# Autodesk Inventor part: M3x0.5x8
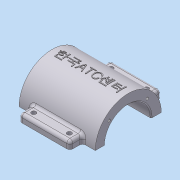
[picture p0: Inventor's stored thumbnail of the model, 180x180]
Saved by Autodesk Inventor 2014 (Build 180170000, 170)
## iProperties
Company: 한국ATC센터
Created: 2009-02
Part Number: M3x0.5x8
Document SubType Name: Modeling
Designer: KYOUNG IL JANG
Density: 2.71 g/cm^3
Mass: 199.243 g
Surface Area: 195.422 cm^2
Volume: 73.5215 cm^3
Material: 알루미늄-6061
Vendor: CBT Solutions
Appearance: 알루미늄 - 평지
Author: KYOUNG IL JANG
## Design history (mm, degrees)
sketch "스케치1"
  geometry: L1 (-45, 40)-(45, 40); L2 (45, 40)-(45, -40); L3 (45, -40)-(-45, -40); L4 (-45, -40)-(-45, 40); 3 further points
  constraints: 8 end point, 2 midpoint, 2 parallel, 1 horizontal, 1 horizontal alignment, 1 perpendicular, 1 vertical alignment
  dimensions: "d0" = 90 distance of L2.end L3.end; "d1" = 80 distance of L1.end L2.end
extrude "돌출1" new body sketch "스케치1" distance "d2" = 10; taper "d3" = 0 deg
sketch "스케치2"
  geometry: L1 (40, 0)-(-40, 0) reference; C1 r 32.5 at (0, 80); 2 further points
  constraints: 1 centre point, 1 midpoint, 1 vertical alignment
  dimensions: "d4" = 65 diameter of C1; "d5" = 80 distance from line of C1.centre L1
extrude "돌출2" join sketch "스케치2" stored distance "d6" = 75; taper "d7" = 0 deg
sketch "스케치3"
  geometry: L1 (-7.5, -20)-(7.5, -20); L2 (7.5, 20)-(-7.5, 20); A1 r 20 centre (7.5, 0) between (7.5, -20) and (7.5, 20); A2 r 20 centre (-7.5, 0) between (-7.5, 20) and (-7.5, -20); 2 further points
  constraints: 4 end point, 4 point on circle, 4 tangent, 2 centre point, 1 horizontal, 1 horizontal alignment, 1 midpoint, 1 parallel, 1 vertical alignment
  dimensions: "d8" = 20 radius of A2; "d9" = 55 dimension on A1 A2
extrude "돌출3" join sketch "스케치3" stored distance "d10" = 75; taper "d11" = 0 deg
fillet "모깎기1" dims "d12" = 10
sketch "스케치4"
  geometry: L1 (-45, 0)-(-45, 10) reference; L2 (37.5, 47.5)-(-37.5, 47.5) reference; L3 (-45, 10)-(-27.513, 47.5); 1 further point
  constraints: 2 end point, 1 point on line
  dimensions: "d13" = 25 deg angle of L3 L1
sketch "스케치5"
  geometry: L1 (-40, 0)-(-40, 10) reference; L2 (-40, 10)-(-22.912, 56.95); 2 further points
  constraints: 2 end point, 2 other
  dimensions: "d14" = 20 deg angle of L2 L1
feature "리브1" dims "d15" = 1, "d16" = 6, "d17" = 0
feature "리브2" dims "d18" = 1, "d19" = 6, "d20" = 0
fillet "모깎기2" dims "d21" = 3
fillet "모깎기3" dims "d22" = 3
fillet "모깎기4" dims "d23" = 3
fillet "모깎기5" dims "d24" = 3
fillet "모깎기6" dims "d25" = 3
fillet "모깎기7" dims "d26" = 3
fillet "모깎기8" dims "d27" = 3
sketch "스케치6"
  geometry: A1 r 10 centre (35, -30) between (35, -40) and (45, -30) reference; 1 further point
hole "구멍1" sketch "스케치6" at (35, -30) diameter "d28" = 10; stored, may be unused: countersink angle "d32" = 90 deg, drill point angle "d34" = 118 deg; dims "d29" = 6, "d30" = 4, "d31" = 2, "d33" = 8
hole "구멍2" diameter "d37" = 45; stored, may be unused: countersink angle "d41" = 90 deg, drill point angle "d43" = 118 deg; dims "d35" = 10, "d36" = 10, "d38" = 6, "d39" = 4, "d40" = 2, "d42" = 8
sketch "스케치7"
  geometry: C1 r 22.5 at (0, 0) reference; 2 further points
  dimensions: "d44" = 135 deg dimension on C1.centre point (-18.738, 18.738) point (80, 0); "d45" = 26.5 distance of point (-18.738, 18.738) C1.centre
hole "구멍3" sketch "스케치7" at (-18.738, 18.738) diameter "d46" = 2.459; stored, may be unused: countersink angle "d50" = 90 deg, drill point angle "d52" = 118 deg; dims "d47" = 8, "d48" = 4, "d49" = 2, "d51" = 10
node "작업 평면1"
chamfer "모따기1" distance "d69" = 1; stored, may be unused: second distance "d70" = 2, angle "d71" = 45 deg
sketch "스케치9"
  geometry: L1 (-31.623, 87.5)-(-45, 87.5); L2 (-45, 87.5)-(-45, 72.5); L3 (-45, 72.5)-(-31.623, 72.5); A1 r 32.5 centre (0, 80) between (-31.623, 87.5) and (-31.623, 72.5) reference; 1 further point
  constraints: 6 end point, 2 parallel, 2 point on circle, 1 horizontal, 1 perpendicular
  dimensions: "d73" = 15 distance of L1.end L2.end; "d74" = 45 distance from line of A1.centre L2
extrude "돌출5" join sketch "스케치9" stored distance "d75" = 50; taper "d76" = 0 deg
fillet "모깎기10" dims "d77" = 3
fillet "모깎기11" dims "d78" = 3
sketch "스케치10"
  geometry: L1 (100.378, 66.389)-(0, 66.389); L2 (0, 66.389)-(0, -76.978); L3 (0, -76.978)-(100.378, -76.978); L4 (100.378, -76.978)-(100.378, 66.389); C1 r 32.5 at (0, 0) reference; 1 further point
  constraints: 8 end point, 2 parallel, 1 horizontal, 1 perpendicular, 1 point on line
extrude "돌출6" cut sketch "스케치10" stored distance "d79" = 10; taper "d80" = 0 deg
sketch "스케치11"
  geometry: C1 r 1.621 at (4.5, 4) reference; C2 r 1.621 at (39.5, 4) reference; 1 further point
hole "구멍5" sketch "스케치11" at (39.5, 4), (4.5, 4) diameter "d81" = 4.5; stored, may be unused: countersink angle "d85" = 90 deg, drill point angle "d87" = 118 deg; dims "d82" = 6, "d83" = 4, "d84" = 2, "d86" = 8
node "작업 평면2"
sketch "스케치12"
  geometry: 2 further points
  constraints: 1 coincident, 1 other
feature "엠보싱1" sketch "스케치12" dims "d8" = 20, "d9" = 55, "d88" = 0.5, "d89" = 0
node "솔리드1"
mirror "대칭1"
mirror "대칭2"
mirror "대칭3"
mirror "대칭4"
pattern_circular "원형 패턴1" dims angle "d54" = 360 deg
mirror "대칭5"
mirror "대칭6"
mirror "대칭7"
node "참조1"
node "참조2"
other parameters: "d56" = -117
